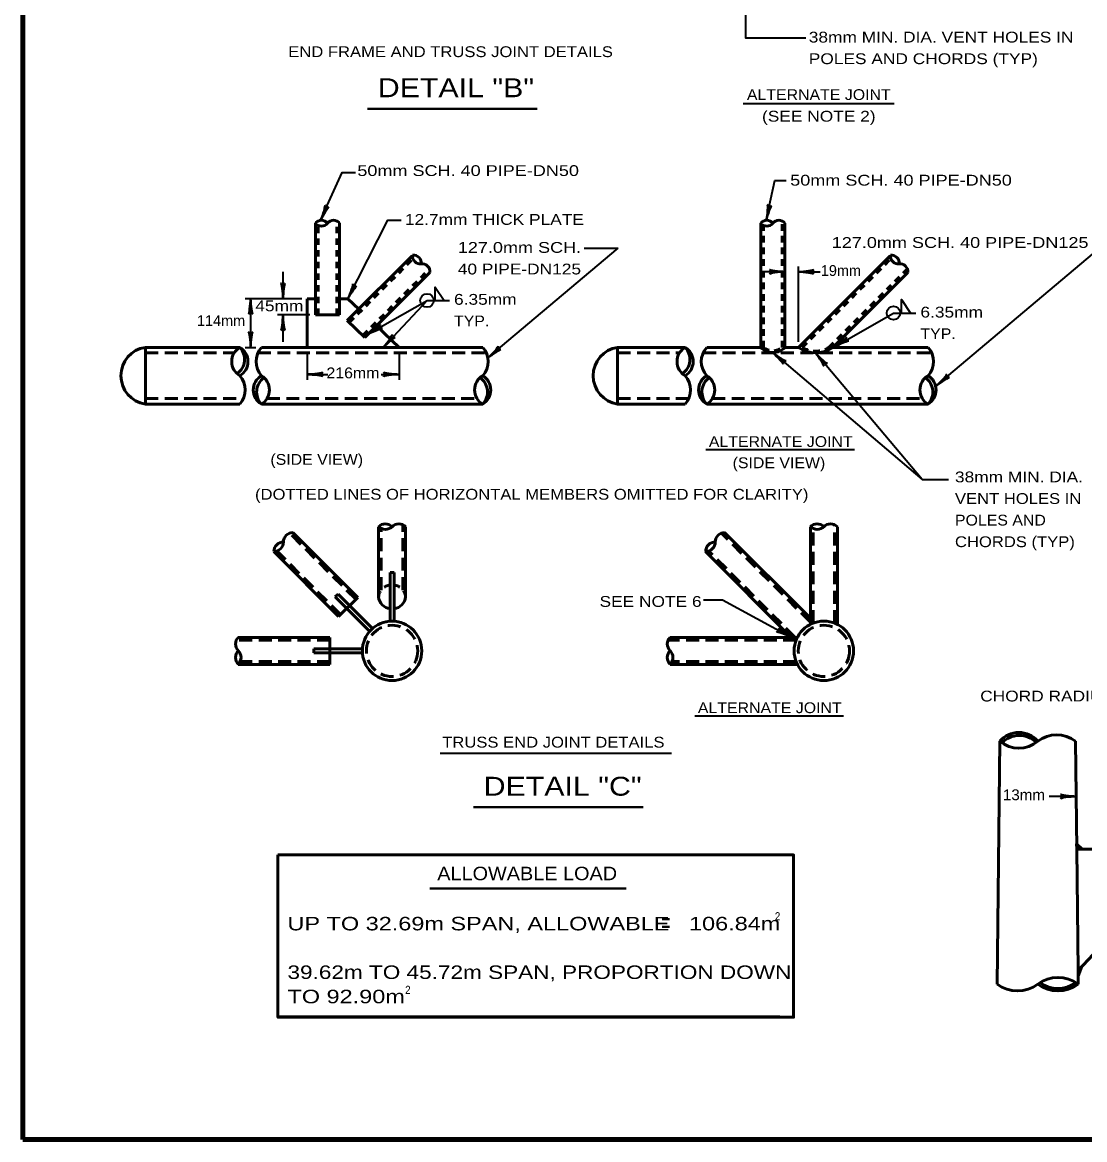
# Model space of a CAD drawing. Extents: x -35 to 821, y -13 to 531.
# Drawn here: x 22.6 to 258.8, y -1 to 247.3 of the extents above; entities that cross this region are included whole.
import ezdxf
from ezdxf.enums import TextEntityAlignment as Align

# ---------------------------------------------------------------- set-up
doc = ezdxf.new("R2010")
doc.units = 0
doc.header["$LTSCALE"] = 0.96
doc.linetypes.add('MEDIUM_DASHED', pattern=[4.5, 3, -1.5])
doc.linetypes.add('SHORT_DASHED', pattern=[2.7, 1.5, -1.2])
doc.layers.add('1', color=7, linetype='Continuous', lineweight=53)

msp = doc.modelspace()

# ---------------------------------------------------------------- linework, layer by layer
at = {"layer": '1', "lineweight": 35}
for p, q in [((182.8294, 229.296), (216.4043, 229.296)), ((126.084, 172.7233), (155.0706, 197.158)), ((147.4893, 197.158), (155.0706, 197.158)), ((225.8081, 166.5182), (263.3752, 198.1859)), ((80.5576, 191.8746), (80.5576, 185.8746)), ((192.1576, 191.8746), (187.3576, 191.8746)), ((195.1576, 176.2746), (195.1576, 193.0746)), ((195.1576, 191.8746), (199.9576, 191.8746)), ((84.7576, 185.8746), (72.1576, 185.8746)), ((73.3576, 185.8746), (73.3576, 175.0746)), ((112.5872, 185.4813), (117.5794, 185.4813)), ((86.5576, 182.2746), (79.3576, 182.2746)), ((80.5576, 182.2746), (80.5576, 176.2746)), ((72.1576, 175.0746), (74.5576, 175.0746)), ((85.9576, 173.8746), (85.9576, 167.8746)), ((106.3576, 173.8746), (106.3576, 167.8746)), ((85.9576, 169.0746), (90.4938, 169.0746)), ((102.3901, 169.0746), (106.3576, 169.0746)), ((174.5903, 152.3622), (207.6262, 152.3622)), ((222.6542, 145.7273), (228.5208, 145.7273)), ((172.148, 93.2064), (205.1839, 93.2064)), ((115.5106, 84.9201), (166.8969, 84.9201)), ((256.868, 75.2576), (250.868, 75.2576))]:
    msp.add_line(p, q, dxfattribs=at)
at = {"layer": '1', "lineweight": 40}
for p, q in [((99.3592, 228.1119), (137.0594, 228.1119)), ((122.8971, 72.8717), (160.5973, 72.8717)), ((113.2167, 54.7687), (156.8576, 54.7687))]:
    msp.add_line(p, q, dxfattribs=at)
at = {"layer": '1'}
for p, q in [((87.7576, 182.2746), (87.7576, 202.6746)), ((93.1576, 182.2746), (93.1576, 202.6746)), ((186.7576, 175.0746), (186.7576, 202.6746)), ((192.1576, 175.0746), (192.1576, 202.6746)), ((94.8584, 181.0245), (109.2834, 195.4495)), ((195.1576, 175.0746), (215.5325, 195.4495)), ((98.7704, 177.3021), (113.1954, 191.7271)), ((202.792, 175.0746), (219.4445, 191.7271)), ((85.9576, 175.0746), (85.9576, 185.8746)), ((85.9576, 185.8746), (87.7576, 185.8746)), ((93.1576, 185.8746), (94.9576, 185.8746)), ((94.9576, 185.8746), (97.3972, 183.5633)), ((87.7576, 182.2746), (93.1576, 182.2746)), ((94.8584, 181.0245), (98.7704, 177.3021)), ((101.3176, 179.8493), (106.3576, 175.0746)), ((49.9576, 175.0746), (49.9576, 162.4746)), ((49.9576, 175.0746), (70.9576, 175.0746)), ((75.7576, 175.0746), (124.9576, 175.0746)), ((154.9576, 175.0746), (154.9576, 162.4746)), ((154.9576, 175.0746), (169.9576, 175.0746)), ((174.7576, 175.0746), (186.7576, 175.0746)), ((192.1576, 175.0746), (195.1576, 175.0746)), ((202.792, 175.0746), (223.9576, 175.0746)), ((49.9576, 162.4746), (70.9576, 162.4746)), ((75.7576, 162.4746), (124.9576, 162.4746)), ((154.9576, 162.4746), (169.9576, 162.4746)), ((174.7576, 162.4746), (223.9576, 162.4746)), ((101.8048, 119.6222), (101.8048, 135.2222)), ((107.8048, 119.6222), (107.8048, 135.2222)), ((197.8048, 113.501), (197.8048, 135.2222)), ((203.8048, 113.501), (203.8048, 135.2222)), ((97.168, 119.5016), (82.743, 133.9266)), ((197.8048, 114.8648), (178.743, 133.9266)), ((92.9254, 115.2589), (78.5004, 129.6839)), ((193.5621, 110.6222), (174.5004, 129.6839)), ((104.3548, 114.2068), (104.3548, 125.0222)), ((104.3548, 125.0222), (105.2548, 125.0222)), ((105.2548, 114.2068), (105.2548, 125.0222)), ((92.1829, 119.6076), (92.8192, 120.2439)), ((92.1829, 119.6076), (99.8306, 111.96)), ((92.8192, 120.2439), (100.4668, 112.5963)), ((92.9254, 115.2589), (97.168, 119.5016)), ((91.0048, 110.6222), (70.6048, 110.6222)), ((91.0048, 104.6222), (91.0048, 110.6222)), ((194.926, 110.6222), (166.6048, 110.6222)), ((98.2048, 108.0722), (87.4048, 108.0722)), ((87.4048, 107.1722), (87.4048, 108.0722)), ((98.2048, 107.1722), (87.4048, 107.1722)), ((91.0048, 104.6222), (70.6048, 104.6222)), ((194.926, 104.6222), (166.6048, 104.6222)), ((239.945, 87.5563), (239.345, 33.5563)), ((256.7446, 87.5563), (257.0115, 63.5577)), ((257.0116, 63.5577), (256.9982, 64.7576)), ((79.4478, 62.2754), (191.0478, 62.2754)), ((257.0115, 63.5577), (270.2116, 63.5577)), ((257.0115, 63.5577), (257.3117, 36.556)), ((270.2116, 50.3577), (257.3117, 36.5559)), ((257.3251, 35.3562), (257.3118, 36.5561)), ((257.3119, 36.556), (257.3454, 33.5399))]:
    msp.add_line(p, q, dxfattribs=at)
at = {"layer": '1', "linetype": 'SHORT_DASHED'}
for p, q in [((88.3576, 182.2746), (88.3576, 202.1897)), ((92.5576, 182.2746), (92.5576, 203.1595)), ((187.3576, 175.0746), (187.3576, 202.1897)), ((191.5576, 175.0746), (191.5576, 203.1595)), ((95.2826, 180.6002), (109.459, 194.7766)), ((196.0061, 175.0746), (215.7081, 194.7766)), ((98.3461, 177.7263), (113.1141, 192.4943)), ((201.9435, 175.0746), (219.3632, 192.4943))]:
    msp.add_line(p, q, dxfattribs=at)
at = {"layer": '1', "linetype": 'MEDIUM_DASHED'}
for p, q in [((49.9576, 173.8746), (69.7236, 173.8746)), ((74.9821, 173.8746), (125.7331, 173.8746)), ((154.9576, 173.8746), (168.7236, 173.8746)), ((173.9821, 173.8746), (224.7331, 173.8746)), ((49.9576, 163.6746), (71.7331, 163.6746)), ((76.9916, 163.6746), (123.7236, 163.6746)), ((154.9576, 163.6746), (170.7331, 163.6746)), ((175.9916, 163.6746), (222.7236, 163.6746)), ((102.4048, 121.1332), (102.4048, 134.8389)), ((107.2048, 121.1332), (107.2048, 135.6498)), ((198.4048, 113.7704), (198.4048, 134.8389)), ((203.2048, 113.7704), (203.2048, 135.6498)), ((96.7437, 119.0773), (82.0276, 133.7934)), ((197.8048, 114.0162), (178.0276, 133.7934)), ((93.3496, 115.6831), (79.206, 129.8267)), ((194.4105, 110.6222), (175.206, 129.8267)), ((91.0048, 110.0222), (70.1932, 110.0222)), ((194.6566, 110.0222), (166.1932, 110.0222)), ((91.0048, 105.2222), (71.0029, 105.2222)), ((194.6566, 105.2222), (167.0029, 105.2222))]:
    msp.add_line(p, q, dxfattribs=at)
at = {"layer": '1', "lineweight": 158}
msp.add_line((814.3112, -1.0154), (22.7112, -1.0154), dxfattribs=at)
msp.add_lwpolyline([(814.3112, 525.0846), (22.6112, 524.9846), (22.7112, -1.0154)], dxfattribs=at)
at = {"layer": '1', "lineweight": 35}
for points in [[(183.3567, 285.4461), (183.3567, 243.8761), (196.8044, 243.8761)], [(88.9292, 203.323), (93.7278, 213.9707), (96.705, 213.9707)], [(188.0002, 203.3289), (189.9069, 212.1721), (192.4586, 212.1721)], [(94.9576, 185.8746), (103.8493, 203.3355), (106.8262, 203.3355)], [(114.3872, 185.4813), (114.3872, 188.4813), (116.3794, 185.4813)], [(99.4493, 177.981), (112.5872, 185.4813), (102.8341, 175.0746)], [(218.0926, 182.7079), (218.0926, 185.7079), (220.0848, 182.7079)], [(203.1547, 175.2076), (216.2926, 182.7079), (221.2848, 182.7079)], [(189.4576, 173.8972), (222.6542, 145.7273), (198.9748, 173.8358)], [(193.5621, 110.6222), (178.2779, 118.8842), (174.065, 118.8842)]]:
    msp.add_lwpolyline(points, dxfattribs=at)
at = {"layer": '1'}
for points in [[(256.9982, 64.7576), (258.2115, 63.5577), (257.0115, 63.5577)], [(79.4478, 62.2754), (79.4478, 26.2754), (191.0478, 26.2754)], [(257.3118, 36.5561), (258.1314, 37.4331), (257.3252, 35.3563)]]:
    msp.add_lwpolyline(points, dxfattribs=at)
msp.add_lwpolyline([(79.4478, 62.2754), (194.062, 62.2754), (194.062, 26.19), (79.4478, 26.19)], close=True, dxfattribs=at)
at = {"layer": '1', "lineweight": 35}
for centre in [(112.5872, 185.4813), (216.2926, 182.7079)]:
    msp.add_circle(centre, 1.5, dxfattribs=at)
at = {"layer": '1'}
for centre in [(104.8048, 107.6222), (200.8048, 107.6222)]:
    msp.add_circle(centre, 6.6, dxfattribs=at)
at = {"layer": '1', "linetype": 'MEDIUM_DASHED'}
for centre in [(104.8048, 107.6222), (200.8048, 107.6222)]:
    msp.add_circle(centre, 5.7, dxfattribs=at)
at = {"layer": '1'}
for centre, radius, start, end in [((89.1076, 201.618), 1.7144, 38.05019, 141.94981), ((89.1076, 203.7312), 1.7144, 218.05019, 321.94981), ((91.8076, 201.618), 1.7144, 38.05019, 141.94981), ((188.1076, 201.618), 1.7144, 38.05019, 141.94981), ((188.1076, 203.7312), 1.7144, 218.05019, 321.94981), ((190.8076, 201.618), 1.7144, 38.05019, 141.94981), ((111.0788, 195.338), 1.7144, 173.05019, 276.94981), ((109.5845, 193.8437), 1.7144, 353.05019, 96.94981), ((217.3279, 195.338), 1.7144, 173.05019, 276.94981), ((215.8336, 193.8437), 1.7144, 353.05019, 96.94981), ((111.4937, 191.9345), 1.7144, 353.05019, 96.94981), ((217.7428, 191.9345), 1.7144, 353.05019, 96.94981), ((50.8836, 168.7746), 6.3677, 98.36152, 261.63848), ((72.8241, 171.9246), 3.6627, 120.68034, 239.31966), ((68.127, 172.3975), 3.8961, 305.07997, 43.40311), ((69.1061, 171.9246), 3.6538, 300.42408, 59.55399), ((79.3157, 171.9246), 4.7521, 138.48126, 221.51873), ((121.3995, 171.9246), 4.7521, 318.48127, 41.51874), ((155.8836, 168.7746), 6.3677, 98.36152, 261.63848), ((171.8241, 171.9246), 3.6627, 120.68034, 239.31966), ((167.127, 172.3975), 3.8961, 305.07997, 43.40311), ((168.1061, 171.9246), 3.6538, 300.42408, 59.55399), ((178.3157, 171.9246), 4.7521, 138.48126, 221.51873), ((189.4576, 177.5818), 3.6846, 222.88007, 317.11993), ((198.9748, 180.3364), 6.5005, 234.04055, 305.95944), ((220.3995, 171.9246), 4.7521, 318.48127, 41.51874), ((67.3995, 165.6246), 4.7521, 318.48126, 41.51873), ((77.6091, 165.6246), 3.6538, 120.42408, 239.55399), ((78.5882, 165.1517), 3.8961, 125.07997, 223.40311), ((73.8911, 165.6246), 3.6627, 300.68034, 59.31966), ((126.8241, 165.6246), 3.6627, 120.68034, 239.31966), ((122.127, 165.1517), 3.8961, 316.59689, 54.92003), ((123.1061, 165.6246), 3.6538, 300.44601, 59.57592), ((166.3995, 165.6246), 4.7521, 318.48126, 41.51873), ((176.6091, 165.6246), 3.6538, 120.42408, 239.55399), ((177.5882, 165.1517), 3.8961, 125.07997, 223.40311), ((172.8911, 165.6246), 3.6627, 300.68034, 59.31966), ((225.8241, 165.6246), 3.6627, 120.68034, 239.31966), ((221.127, 165.1517), 3.8961, 316.59689, 54.92003), ((222.1061, 165.6246), 3.6538, 300.44601, 59.57592), ((103.3048, 133.752), 2.1004, 44.42571, 135.57429), ((103.3346, 136.7222), 2.1004, 224.42571, 315.57429), ((106.3048, 133.752), 2.1004, 44.42571, 135.57429), ((199.3048, 133.752), 2.1004, 44.42571, 135.57429), ((199.3346, 136.7222), 2.1004, 224.42571, 315.57429), ((202.3048, 133.752), 2.1004, 44.42571, 135.57429), ((80.6427, 129.705), 2.1004, 89.42571, 180.57429), ((78.5635, 131.8263), 2.1004, 269.42571, 0.57429), ((82.764, 131.8263), 2.1004, 89.42571, 180.57429), ((176.6427, 129.705), 2.1004, 89.42571, 180.57429), ((174.5635, 131.8263), 2.1004, 269.42571, 0.57429), ((178.764, 131.8263), 2.1004, 89.42571, 180.57429), ((104.8048, 119.9389), 3.0167, 186.02558, 261.4211), ((104.8048, 119.9389), 3.0167, 278.5789, 353.97442), ((72.1048, 109.152), 2.1004, 134.42571, 225.57429), ((168.1048, 109.152), 2.1004, 134.42571, 225.57429), ((72.1048, 106.152), 2.1004, 134.42571, 225.57429), ((69.1346, 106.1818), 2.1004, 314.42571, 45.57429), ((168.1048, 106.152), 2.1004, 134.42571, 225.57429), ((165.1346, 106.1818), 2.1004, 314.42571, 45.57429), ((244.145, 83.9482), 5.537, 40.66498, 139.33502), ((244.145, 92.3409), 6.3665, 228.72298, 311.27702), ((244.2514, 83.4804), 5.333, 45.34412, 136.03167), ((252.545, 81.9366), 7.0158, 53.22658, 126.77342), ((252.845, 27.6382), 7.4218, 52.67567, 127.32434), ((243.845, 39.4582), 7.4218, 232.67566, 307.32433), ((252.845, 39.4582), 7.4218, 232.67566, 307.32433), ((252.8667, 39.2007), 6.6284, 232.97178, 306.38302)]:
    msp.add_arc(centre, radius, start, end, dxfattribs=at)
at = {"layer": '1', "linetype": 'SHORT_DASHED'}
for centre, radius, start, end in [((189.4576, 177.5752), 3.2655, 229.97703, 310.02297), ((198.9748, 179.9235), 5.6855, 238.52341, 301.47659), ((104.8048, 119.3055), 3.0167, 98.5789, 173.97442), ((104.8048, 119.3055), 3.0167, 6.02558, 81.4211)]:
    msp.add_arc(centre, radius, start, end, dxfattribs=at)
at = {"layer": '1', "lineweight": 40}
for centre, major_axis, ratio, start_param, end_param in [((89.1649, 204.653), (-0.7096, -2.0306), 0.122415, 0.89635335, 3.14159265), ((89.7132, 204.4445), (1.0582, 1.835), 0.07063, 6.28230741, 8.55970261), ((187.9521, 204.6788), (-0.2685, -2.1342), 0.122415, 0.89635335, 3.14159265), ((188.5318, 204.5898), (0.6503, 2.016), 0.07063, 6.28230741, 8.55970261), ((190.8482, 191.543), (2.1428, 0.1874), 0.122415, 0.89635335, 3.14159265), ((190.813, 192.1285), (2.1077, -0.2108), 0.07063, 3.14071475, 5.41810995), ((196.5022, 191.6207), (-2.1077, 0.2108), 0.07063, 3.14071475, 5.41810995), ((196.467, 192.2062), (-2.1428, -0.1874), 0.122415, 0.89635335, 3.14159265), ((80.226, 187.184), (0.1874, -2.1428), 0.122415, 0.89635335, 3.14159265), ((80.226, 187.184), (0.1874, -2.1428), 0.122415, 0.89635335, 3.14159265), ((80.8115, 187.2192), (-0.2108, -2.1077), 0.07063, 3.14071475, 5.41810995), ((80.8115, 187.2192), (-0.2108, -2.1077), 0.07063, 3.14071475, 5.41810995), ((95.2563, 187.1919), (-0.8054, -1.9945), 0.122415, 0.89635335, 3.14159265), ((95.794, 186.9576), (1.1443, 1.7826), 0.07063, 6.28230741, 8.55970261), ((73.1037, 184.53), (0.2108, 2.1077), 0.07063, 3.14071475, 5.41810995), ((73.1037, 184.53), (0.2108, 2.1077), 0.07063, 3.14071475, 5.41810995), ((73.6892, 184.5652), (-0.1874, 2.1428), 0.122415, 0.89635335, 3.14159265), ((73.6892, 184.5652), (-0.1874, 2.1428), 0.122415, 0.89635335, 3.14159265), ((80.3037, 180.93), (0.2108, 2.1077), 0.07063, 3.14071475, 5.41810995), ((80.8892, 180.9652), (-0.1874, 2.1428), 0.122415, 0.89635335, 3.14159265), ((100.4221, 178.9181), (-1.768, -1.2251), 0.122415, 0.89635335, 3.14159265), ((100.7429, 178.4271), (-1.935, -0.8619), 0.07063, 3.14071475, 5.41810995), ((73.026, 176.384), (0.1874, -2.1428), 0.122415, 0.89635335, 3.14159265), ((73.6115, 176.4192), (-0.2108, -2.1077), 0.07063, 3.14071475, 5.41810995), ((103.4876, 176.2568), (-1.3286, -1.6917), 0.122415, 0.89635335, 3.14159265), ((103.9388, 175.882), (1.5951, 1.3938), 0.07063, 6.28230741, 8.55970261), ((204.1275, 176.1447), (-1.768, -1.2251), 0.122415, 0.89635335, 3.14159265), ((204.4483, 175.6537), (-1.935, -0.8619), 0.07063, 3.14071475, 5.41810995), ((126.8715, 173.8208), (-1.5176, -1.5244), 0.122415, 0.89635335, 3.14159265), ((127.2757, 173.3958), (-1.7474, -1.1973), 0.07063, 3.14071475, 5.41810995), ((190.3185, 172.8336), (-1.4707, 1.5245), 0.07063, 3.14071475, 5.41810995), ((190.3185, 172.8336), (-1.4707, 1.5245), 0.07063, 3.14071475, 5.41810995), ((190.6705, 173.3028), (-1.7551, 1.2436), 0.122415, 0.89635335, 3.14159265), ((190.6705, 173.3028), (-1.7551, 1.2436), 0.122415, 0.89635335, 3.14159265), ((199.6469, 172.6439), (-1.1968, 1.7478), 0.07063, 3.14071475, 5.41810995), ((200.072, 173.048), (-1.5239, 1.5181), 0.122415, 0.89635335, 3.14159265), ((87.3022, 168.8207), (-2.1077, 0.2108), 0.07063, 3.14071475, 5.41810995), ((87.3022, 168.8207), (-2.1077, 0.2108), 0.07063, 3.14071475, 5.41810995), ((87.267, 169.4062), (-2.1428, -0.1874), 0.122415, 0.89635335, 3.14159265), ((87.267, 169.4062), (-2.1428, -0.1874), 0.122415, 0.89635335, 3.14159265), ((105.0482, 168.743), (2.1428, 0.1874), 0.122415, 0.89635335, 3.14159265), ((105.013, 169.3285), (2.1077, -0.2108), 0.07063, 3.14071475, 5.41810995), ((226.5956, 167.6157), (-1.5176, -1.5244), 0.122415, 0.89635335, 3.14159265), ((226.9998, 167.1907), (-1.7474, -1.1973), 0.07063, 3.14071475, 5.41810995), ((192.2525, 110.9532), (1.9742, -0.8541), 0.122415, 0.89635335, 3.14159265), ((192.5, 111.485), (1.7539, -1.1877), 0.07063, 3.14071475, 5.41810995), ((255.5586, 74.926), (2.1428, 0.1874), 0.122415, 0.89635335, 3.14159265), ((255.5586, 74.926), (2.1428, 0.1874), 0.122415, 0.89635335, 3.14159265), ((255.5234, 75.5115), (2.1077, -0.2108), 0.07063, 3.14071475, 5.41810995), ((255.5234, 75.5115), (2.1077, -0.2108), 0.07063, 3.14071475, 5.41810995)]:
    msp.add_ellipse(centre, major_axis=major_axis, ratio=ratio, start_param=start_param, end_param=end_param, dxfattribs=at)

# ---------------------------------------------------------------- texts
at = {"layer": '1'}
for s, height, width, p in [('38mm MIN. DIA. VENT HOLES IN', 2.4, 1.2, (197.4488, 242.826)), ('END FRAME AND TRUSS JOINT DETAILS', 2.4, 1.15, (81.7235, 239.5882)), ('POLES AND CHORDS (TYP)', 2.4, 1.2, (197.4488, 238.026)), ('DETAIL "B"', 4.2, 1.2, (101.6351, 230.6731)), ('50mm SCH. 40 PIPE-DN50', 2.4, 1.25, (97.0855, 213.1593)), ('50mm SCH. 40 PIPE-DN50', 2.4, 1.25, (193.3208, 211.0281)), ('12.7mm THICK PLATE', 2.4, 1.2, (107.6564, 202.3018)), ('127.0mm SCH. 40 PIPE-DN125', 2.4, 1.25, (202.5537, 197.1753)), ('127.0mm SCH.', 2.4, 1.25, (119.4234, 196.0837)), ('40 PIPE-DN125', 2.4, 1.2, (119.4234, 191.2837)), ('6.35mm', 2.4, 1.2, (118.5824, 184.5456)), ('45mm', 2.4, 1.2, (74.4027, 183.098)), ('6.35mm', 2.4, 1.2, (222.2751, 181.704)), ('TYP.', 2.4, 1.1, (118.5824, 179.7456)), ('TYP.', 2.4, 1.1, (222.2751, 176.904)), ('216mm', 2.4, 1.1, (90.2245, 168.2016)), ('ALTERNATE JOINT', 2.4, 1.1, (175.2355, 152.9352)), ('(SIDE VIEW)', 2.4, 1.1, (77.7634, 148.969)), ('(SIDE VIEW)', 2.4, 1.1, (180.5221, 148.2199)), ('38mm MIN. DIA.', 2.4, 1.2, (229.9511, 145.0751)), ('(DOTTED LINES OF HORIZONTAL MEMBERS OMITTED FOR CLARITY)', 2.4, 1.15, (74.3422, 141.2239)), ('VENT HOLES IN', 2.4, 1.15, (229.9511, 140.2751)), ('POLES AND', 2.4, 1.1, (229.9511, 135.4751)), ('CHORDS (TYP)', 2.4, 1.15, (229.9511, 130.6751)), ('SEE NOTE 6', 2.4, 1.2, (150.9347, 117.3962)), ('CHORD RADIUS   1.6mm', 2.4, 1.2, (235.5632, 96.3723)), ('ALTERNATE JOINT', 2.4, 1.1, (172.7932, 93.7794)), ('TRUSS END JOINT DETAILS', 2.4, 1.15, (115.9563, 86.1218)), ('DETAIL "C"', 4.2, 1.2, (125.173, 75.4329)), ('13mm', 2.4, 1.05, (240.6108, 74.4319)), ('ALLOWABLE LOAD', 3, 1.1, (114.8583, 56.6454)), ('UP TO 32.69m SPAN, ALLOWABLE   106.84m', 3, 1.3, (81.5584, 45.4985)), ('=', 4.8, 0.55, (164.6637, 44.835)), ('2', 1.8, 0.9, (189.9137, 47.7378)), ('39.62m TO 45.72m SPAN, PROPORTION DOWN', 3, 1.25, (81.5584, 34.6985)), ('TO 92.90m', 3, 1.3, (81.5584, 29.2985)), ('2', 1.8, 0.9, (107.7192, 31.374))]:
    msp.add_text(s, height=height, dxfattribs=dict(at, width=width)).set_placement(p)
for s, width, p in [('ALTERNATE JOINT', 1.1, (199.6815, 230.0476)), ('(SEE NOTE 2)', 1.2, (199.6816, 225.2476))]:
    msp.add_text(s, height=2.4, dxfattribs=dict(at, width=width)).set_placement(p, align=Align.CENTER)
for s, p in [('19mm', (200.1365, 190.9492)), ('114mm', (61.4497, 179.8257))]:
    msp.add_text(s, height=2.4, dxfattribs=at).set_placement(p)

doc.saveas('drawing.dxf')
